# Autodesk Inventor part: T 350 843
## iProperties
Company: Mayer & Müller AG Schaltgeräte
Created: 2006-10
Part Number: T 350 843
Material: 2.0060.30
Document SubType Name: Modeling
Designer: I.Baliuc
Manufacturer: Standard
Standards Organization: Custom
Description: Anschlußfahne
Density: 8.94 g/cm^3
HalbzeugNorm: DIN 1759
Zweck: für festen Vorkontakt
Abmessung: 60 x 6 - 20
Author: T.Messerschmitt
Revision Number: 350843
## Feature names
1. Extrusion2
2. Bohrung1 [Hole]
3. Fase1 [Chamfer]
